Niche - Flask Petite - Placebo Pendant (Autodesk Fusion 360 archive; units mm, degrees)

design "Flask - Petite - Modular" references "Modular - Placebo - Bayonet Connector", "Modular - Placedo - Cord Set"
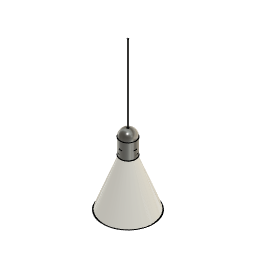
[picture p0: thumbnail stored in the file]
sketch "Sketch1" plane through (0, 0, 0) normal (0, 1, 0) x axis (1, 0, 0)
  line L1 (0, 76.2) -> (0, -139.7)
  line L2 (95.25, 50.8) -> (95.25, -139.7)
  line L3 (76.2, 0) -> (-63.5, 0)
  line L4 (76.2, -127) -> (-63.5, -127)
  line L5 (26.924, 63.5) -> (26.924, -139.7)
  line L6 (-95.25, 50.8) -> (-95.2517, -127.0009)
  line L7 (26.924, -139.7) -> (-26.924, -139.7)
  line L8 (26.924, -139.7) -> (26.924, -139.7)
  line L9 (60.579, 76.2) -> (-60.579, 76.2)
  line L10 (95.25, 50.8) -> (-95.25, 50.8)
  line L11 (95.25, 50.8) -> (26.924, -127)
  line L12 (-26.924, 63.5) -> (-26.924, -139.7)
  line L13 (-95.25, 50.8) -> (-26.924, -127)
  arc A1 centre (0, -115.0938) radius 191.2938 clockwise from (-95.25, 50.8) to (95.25, 50.8)
  point P14 (0, -139.7)
  point P17 (26.924, -127)
  point P8 (26.924, -139.7)
  point P19 (-26.924, -139.7)
  point P21 (-26.924, -127)
  point P23 (0, 76.2)
  point P11 (-95.25, 50.8)
  point P22 (-95.25, 50.8)
  vertical L1
  perpendicular L2 L3
  perpendicular L5 L7
  perpendicular L4 L8
  coincident L7 P14
  coincident L4 P17
  coincident L5 P17
  tangent L9 A1
  symmetric L1 P8 P19
  symmetric L1 P17 P21
  coincident L9 P23
  coincident P11 P22
  dimension "d1" = 95.25
  dimension "d2" = 127
  dimension "d3" = 26.924
revolve "Revolve1" sketch "Sketch1" AlongAngle 360 bodies "Flask Petite Modular"
shell "Shell1" innerThickness 1.905
component_insert "Component Insert1"
component_from_bodies "Body->Comp"
component_insert "Component Insert2"
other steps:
base_feature "Base Feature" bodies "Flask Petite Modular"
create_component "CreateComponent1"
remove_body "RemoveBody1"
named bodies: "Flask Petite Modular"

design "Modular - Placebo - Bayonet Connector"
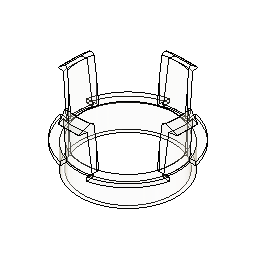
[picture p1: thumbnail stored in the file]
sketch "Sketch1" plane through (0, 0, 0) normal (0, 0, 1) x axis (1, 0, 0)
  circle C1 centre (0, 0) radius 23.241
  point P1 (0, 0)
  point P2 (0, 0)
  coincident P1 P2
  dimension "d1" diameter C1 = 46.482
extrude "Extrude1" new body sketch "Sketch1" along normal blind 11.176
sketch "Sketch2" plane through (0, 0, 11.176) normal (0, 0, 1) x axis (-1, 0, 0)
  line L1 (-23.2795, -6.35) -> (-26.1645, -6.35)
  line L2 (-23.2795, 6.35) -> (-26.1645, 6.35)
  line L3 (26.1645, -6.35) -> (23.2795, -6.35)
  line L4 (26.1645, 6.35) -> (23.2795, 6.35)
  line L5 (6.35, -23.2795) -> (6.35, -26.1645)
  line L6 (-6.35, -23.2795) -> (-6.35, -26.1645)
  line L7 (6.35, 26.1645) -> (6.35, 23.2795)
  line L8 (-6.35, 26.1645) -> (-6.35, 23.2795)
  line L9 (0, -24.13) -> (0, -26.924)
  line L10 (6.35, -23.2795) -> (6.35, -22.3567)
  line L11 (-6.35, -23.2795) -> (-6.35, -22.3567)
  line L12 (23.2795, -6.35) -> (22.3567, -6.35)
  line L13 (23.2795, 6.35) -> (22.3567, 6.35)
  line L14 (-23.2795, 6.35) -> (-22.3567, 6.35)
  line L15 (-23.2795, -6.35) -> (-22.3567, -6.35)
  line L16 (6.35, 22.3567) -> (6.35, 23.2795)
  line L17 (-6.35, 22.3567) -> (-6.35, 23.2795)
  circle C1 centre (0, 0) radius 23.241
  arc A1 centre (0, 0) radius 26.924 clockwise from (-6.35, -26.1645) to (-26.1645, -6.35)
  arc A2 centre (0, 0) radius 26.924 clockwise from (26.1645, -6.35) to (6.35, -26.1645)
  arc A3 centre (0, 0) radius 24.13 clockwise from (23.2795, 6.35) to (23.2795, -6.35)
  arc A4 centre (0, 0) radius 24.13 clockwise from (6.35, -23.2795) to (-6.35, -23.2795)
  arc A5 centre (0, 0) radius 26.924 clockwise from (6.35, 26.1645) to (26.1645, 6.35)
  arc A6 centre (0, 0) radius 26.924 clockwise from (-26.1645, 6.35) to (-6.35, 26.1645)
  arc A7 centre (0, 0) radius 24.13 clockwise from (-6.35, 23.2795) to (6.35, 23.2795)
  arc A8 centre (0, 0) radius 24.13 clockwise from (-23.2795, -6.35) to (-23.2795, 6.35)
  point P2 (0, 0)
  point P4 (0, 0)
  point P12 (-23.2795, -6.35)
  point P13 (-22.3567, -6.35)
  point P14 (-23.2795, 6.35)
  point P15 (-22.3567, 6.35)
  point P16 (22.3567, -6.35)
  point P18 (22.3567, 6.35)
  point P24 (6.35, 23.2795)
  point P28 (6.35, -22.3567)
  point P29 (-6.35, -22.3567)
  point P31 (-6.35, 26.1645)
  point P35 (0, -24.13)
  point P36 (6.35, 22.3567)
  point P37 (-6.35, 22.3567)
  coincident P2 P4
  vertical L9
  concentric A2 A3
  concentric A1 A2
  coincident P12 A3
  coincident C1 P13
  coincident P14 A3
  coincident C1 P15
  coincident C1 P16
  coincident C1 P18
  concentric A2 A5
  coincident P24 L5
  concentric A3 A7
  concentric A4 A7
  coincident C1 P28
  coincident C1 P29
  coincident P31 A5
  concentric A5 A6
  concentric A7 A8
  coincident A4 P35
  horizontal L12
  coincident C1 P36
  parallel L7 L16
  coincident C1 P37
  parallel L8 L17
  dimension "d4" diameter A2 = 53.848
extrude "Extrude2" add sketch "Sketch2" profile of C1 A8 L10 L11 L12 L13 L14 L15 L16 L17 along normal blind 0.762
extrude "Extrude3" add sketch "Sketch2" profile of C1 A6 L7 L8 L4 L3 L10 L11 L12 L13 L14 L15 L16 L17 along normal blind 1.7018
extrude "Extrude4" add sketch "Sketch2" profile of C1 along normal blind 1.7018
work_plane "WorkPlane1" AlongDistance 33.8963
sketch "Sketch3" plane through (0, 0, 33.8963) normal (0, 0, 1) x axis (1, 0, 0)
  line L1 (0, 20.3925) -> (0, 27.5045)
  line L2 (-6.604, 20.3925) -> (-6.604, 27.5045)
  line L3 (6.604, 20.3925) -> (6.604, 27.5045)
  circle C1 centre (0, 0) radius 23.7363
  circle C2 centre (0, 0) radius 27.305
  arc A1 centre (0.0021, 0.2001) radius 23.9364 clockwise from (-6.604, 23.2068) to (6.604, 23.208)
  arc A2 centre (0.0021, 0.2001) radius 21.3964 clockwise from (-6.604, 20.5511) to (6.604, 20.5525)
  point P1 (0, 0)
  point P2 (0, 0)
  point P6 (-6.604, 27.5045)
  point P8 (6.604, 27.5045)
  point P7 (-6.604, 20.3925)
  point P9 (6.604, 20.3925)
  point P11 (-6.604, 23.2068)
  point P12 (6.604, 23.208)
  point P14 (-6.604, 20.5511)
  point P15 (6.604, 20.5525)
  coincident P1 P2
  concentric C1 C2
  vertical L1
  symmetric L1 P6 P8
  symmetric L1 P7 P9
  tangent C1 A1
  coincident L2 P11
  coincident L3 P12
  concentric A1 A2
  coincident L2 P14
  coincident L3 P15
  dimension "d14" diameter C1 = 47.4726
  dimension "d15" diameter C2 = 54.61
  dimension "d16" = 6.604
extrude "Extrude5" new body sketch "Sketch3" profile of C1 L1 L2 L3 A1 A2 against normal blind 21.59
sketch "Sketch4" plane through (0, 0, 33.8963) normal (0, 0, 1) x axis (-1, 0, 0)
  line L1 (6.604, -20.5511) -> (6.604, -23.2068)
  line L2 (-6.604, -23.208) -> (-6.604, -20.5525)
  line L3 (-5.08, -26.67) -> (-6.604, -20.5525)
  line L4 (5.08, -26.67) -> (-5.08, -26.67)
  line L5 (6.604, -20.5511) -> (5.08, -26.67)
  arc A1 centre (-0.0021, -0.2001) radius 23.9364 clockwise from (6.604, -23.2068) to (-6.604, -23.208)
  arc A2 centre (-0.0021, -0.2001) radius 21.3964 clockwise from (6.604, -20.5511) to (-6.604, -20.5525)
  point P6 (-6.604, -20.5525)
  point P7 (-6.604, -20.5525)
  point P5 (6.604, -20.5511)
  point P10 (6.604, -20.5511)
  coincident P6 P7
  perpendicular L2 L4
  coincident P5 P10
extrude "Extrude6" add sketch "Sketch4" profile of A1 A2 L3 L4 L5 against normal blind 3.175
move "Move1"
sketch "Sketch5" plane through (0, 3.4565, 35.8974) normal (0, 0.0958, 0.9954) x axis (-1, 0, 0)
  line L1 (6.604, -19.277) -> (6.604, -21.9327)
  line L2 (-6.604, -21.9339) -> (-6.604, -19.2784)
  line L3 (-5.08, -25.3959) -> (-5.8947, -22.1257)
  line L4 (5.08, -25.3959) -> (-5.08, -25.3959)
  line L5 (5.8948, -22.1246) -> (5.08, -25.3959)
  line L6 (-8.1218, -17.3223) -> (-6.0831, -25.506)
  line L7 (-0.004, -17.3223) -> (-0.0002, -17.3223)
  line L8 (-8.1218, -17.3223) -> (-6.8295, -17.3223)
  line L9 (0, -25.3959) -> (0.0001, -20.3223)
  line L10 (-6.8295, -17.3223) -> (-4.7917, -25.5025)
  line L11 (8.1222, -17.3227) -> (6.0831, -25.5062)
  line L12 (8.1222, -17.3227) -> (6.8299, -17.3226)
  line L13 (-4.7917, -25.5025) -> (-6.1096, -25.506)
  line L14 (4.7917, -25.5027) -> (6.0831, -25.5062)
  line L15 (6.8299, -17.3226) -> (4.7917, -25.5027)
  arc A1 centre (-0.0021, 1.074) radius 23.9364 clockwise from (6.604, -21.9327) to (5.8948, -22.1246)
  arc A2 centre (-0.0021, 1.074) radius 21.3964 clockwise from (6.604, -19.277) to (-6.604, -19.2784)
  arc A3 centre (-0.0021, 1.074) radius 23.9364 clockwise from (-5.8947, -22.1257) to (-6.604, -21.9339)
  arc A4 centre (-0.0021, 1.074) radius 18.3964 clockwise from (5.6778, -16.4236) to (-5.6783, -16.4247)
  point P14 (-0.0002, -17.3223)
  point P15 (-8.1218, -17.3223)
  point P16 (-0.004, -17.3223)
  point P17 (0.0001, -20.3223)
  point P18 (0, -25.3959)
  point P20 (8.1222, -17.3227)
  point P19 (-6.8295, -17.3223)
  point P21 (6.8299, -17.3226)
  point P23 (-6.0831, -25.506)
  point P26 (6.8299, -17.3226)
  point P24 (-4.7917, -25.5025)
  point P25 (4.7917, -25.5027)
  midpoint A4 P14
  horizontal L7
  coincident P15 L7
  coincident A4 P16
  collinear L7 L8
  midpoint A2 P17
  midpoint L4 P18
  symmetric P15 L9 P20
  symmetric L9 P19 P21
  coincident L13 P23
  symmetric L9 P19 P26
  symmetric L9 P24 P25
  dimension "d22" = -3
extrude "Extrude7" cut sketch "Sketch5" profile of A1 L1 A2 L2 A3 L3 L4 L5 L8 L6 L10 L11 L12 L13 L14 L15 against normal blind 25.146 taper -1.45
remove_body "RemoveBody1"
remove_body "RemoveBody2"
chamfer "Chamfer1" sketch "Sketch4" distance 4.572 distance 3.048
circular_pattern "C-Pattern1" TotalAngle 360
extrude "Extrude8" add sketch "Sketch4" along a picked direction blind 0.508
extrude "Extrude9" add of existing geometry blind 0.508
extrude "Extrude10" add of existing geometry blind 0.508
extrude "Extrude11" add of existing geometry blind 0.508
hole "Hole1" sketch "Sketch4" HoleDepth 38.1 HoleDiameter 42.926 TipAngle 118
fillet "Fillet1" sketch "Sketch4" radius 1.27

design "Modular - Placedo - Cord Set"
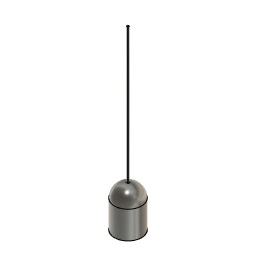
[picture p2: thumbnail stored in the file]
sketch "Sketch1" plane through (0, 0, 0) normal (0, 1, 0) x axis (1, 0, 0)
  line L1 (0, -88.9) -> (0, 0)
  line L2 (-29.5402, -88.9) -> (-29.5402, 0)
  line L3 (29.5402, -88.9) -> (29.5402, 0)
  line L4 (29.5402, 8.5598) -> (29.5402, -59.3598)
  line L5 (-29.5402, -59.3598) -> (-29.5402, 8.5598)
  line L6 (0, 38.1) -> (0, -88.9)
  line L7 (29.5402, 0) -> (-29.5402, 0)
  arc A1 centre (0, 8.5598) radius 29.5402 clockwise from (-29.5402, 8.5598) to (29.5402, 8.5598)
  arc A2 centre (0, -59.3598) radius 29.5402 clockwise from (29.5402, -59.3598) to (-29.5402, -59.3598)
  point P1 (0, 0)
  point P2 (0, 0)
  point P4 (-29.5402, 0)
  point P6 (29.5402, 0)
  point P5 (-29.5402, -88.9)
  point P7 (29.5402, -88.9)
  point P3 (0, -88.9)
  point P14 (0, 38.1)
  coincident P1 P2
  vertical L1
  symmetric L1 P4 P6
  symmetric L1 P5 P7
  tangent L4 A1
  tangent A1 L5
  parallel L4 L5
  tangent L5 A2
  tangent L4 A2
  midpoint P3 A2
  midpoint A1 P14
  parallel L1 L6
  dimension "d1" = 29.5402
revolve "Revolve1" sketch "Sketch1" AlongAngle 360
shell "Shell1" innerThickness 1.524
sketch "Sketch2" plane through (0, 0, 0) normal (0, 0, 1) x axis (1, 0, 0)
  circle C1 centre (0, 0) radius 2.8575
  point P1 (0, 0)
  point P2 (0, 0)
  coincident P1 P2
  dimension "d4" diameter C1 = 5.715
extrude "Extrude1" cut sketch "Sketch2" along normal blind 101.6
sketch "Sketch3" plane through (0, 0, 0) normal (0, 0, 1) x axis (1, 0, 0)
  circle C1 centre (0, 0) radius 2.286
  point P1 (0, 0)
  point P2 (0, 0)
  coincident P1 P2
  dimension "d7" diameter C1 = 4.572
extrude "Extrude2" new body sketch "Sketch3" along normal blind 304.8
move "Move1"
sketch "Sketch4" plane through (0, 0, 0) normal (0, 0, 1) x axis (1, 0, 0)
  circle C1 centre (0, 0) radius 18.796
  point P1 (0, 0)
  point P2 (0, 0)
  coincident P1 P2
  dimension "d10" diameter C1 = 37.592
extrude "Extrude3" new body sketch "Sketch4" along normal blind 31.75
move "Move2"
offset_faces "OffsetFaces1" distance 38.1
